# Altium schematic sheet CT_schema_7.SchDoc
size 371 x 336 mm
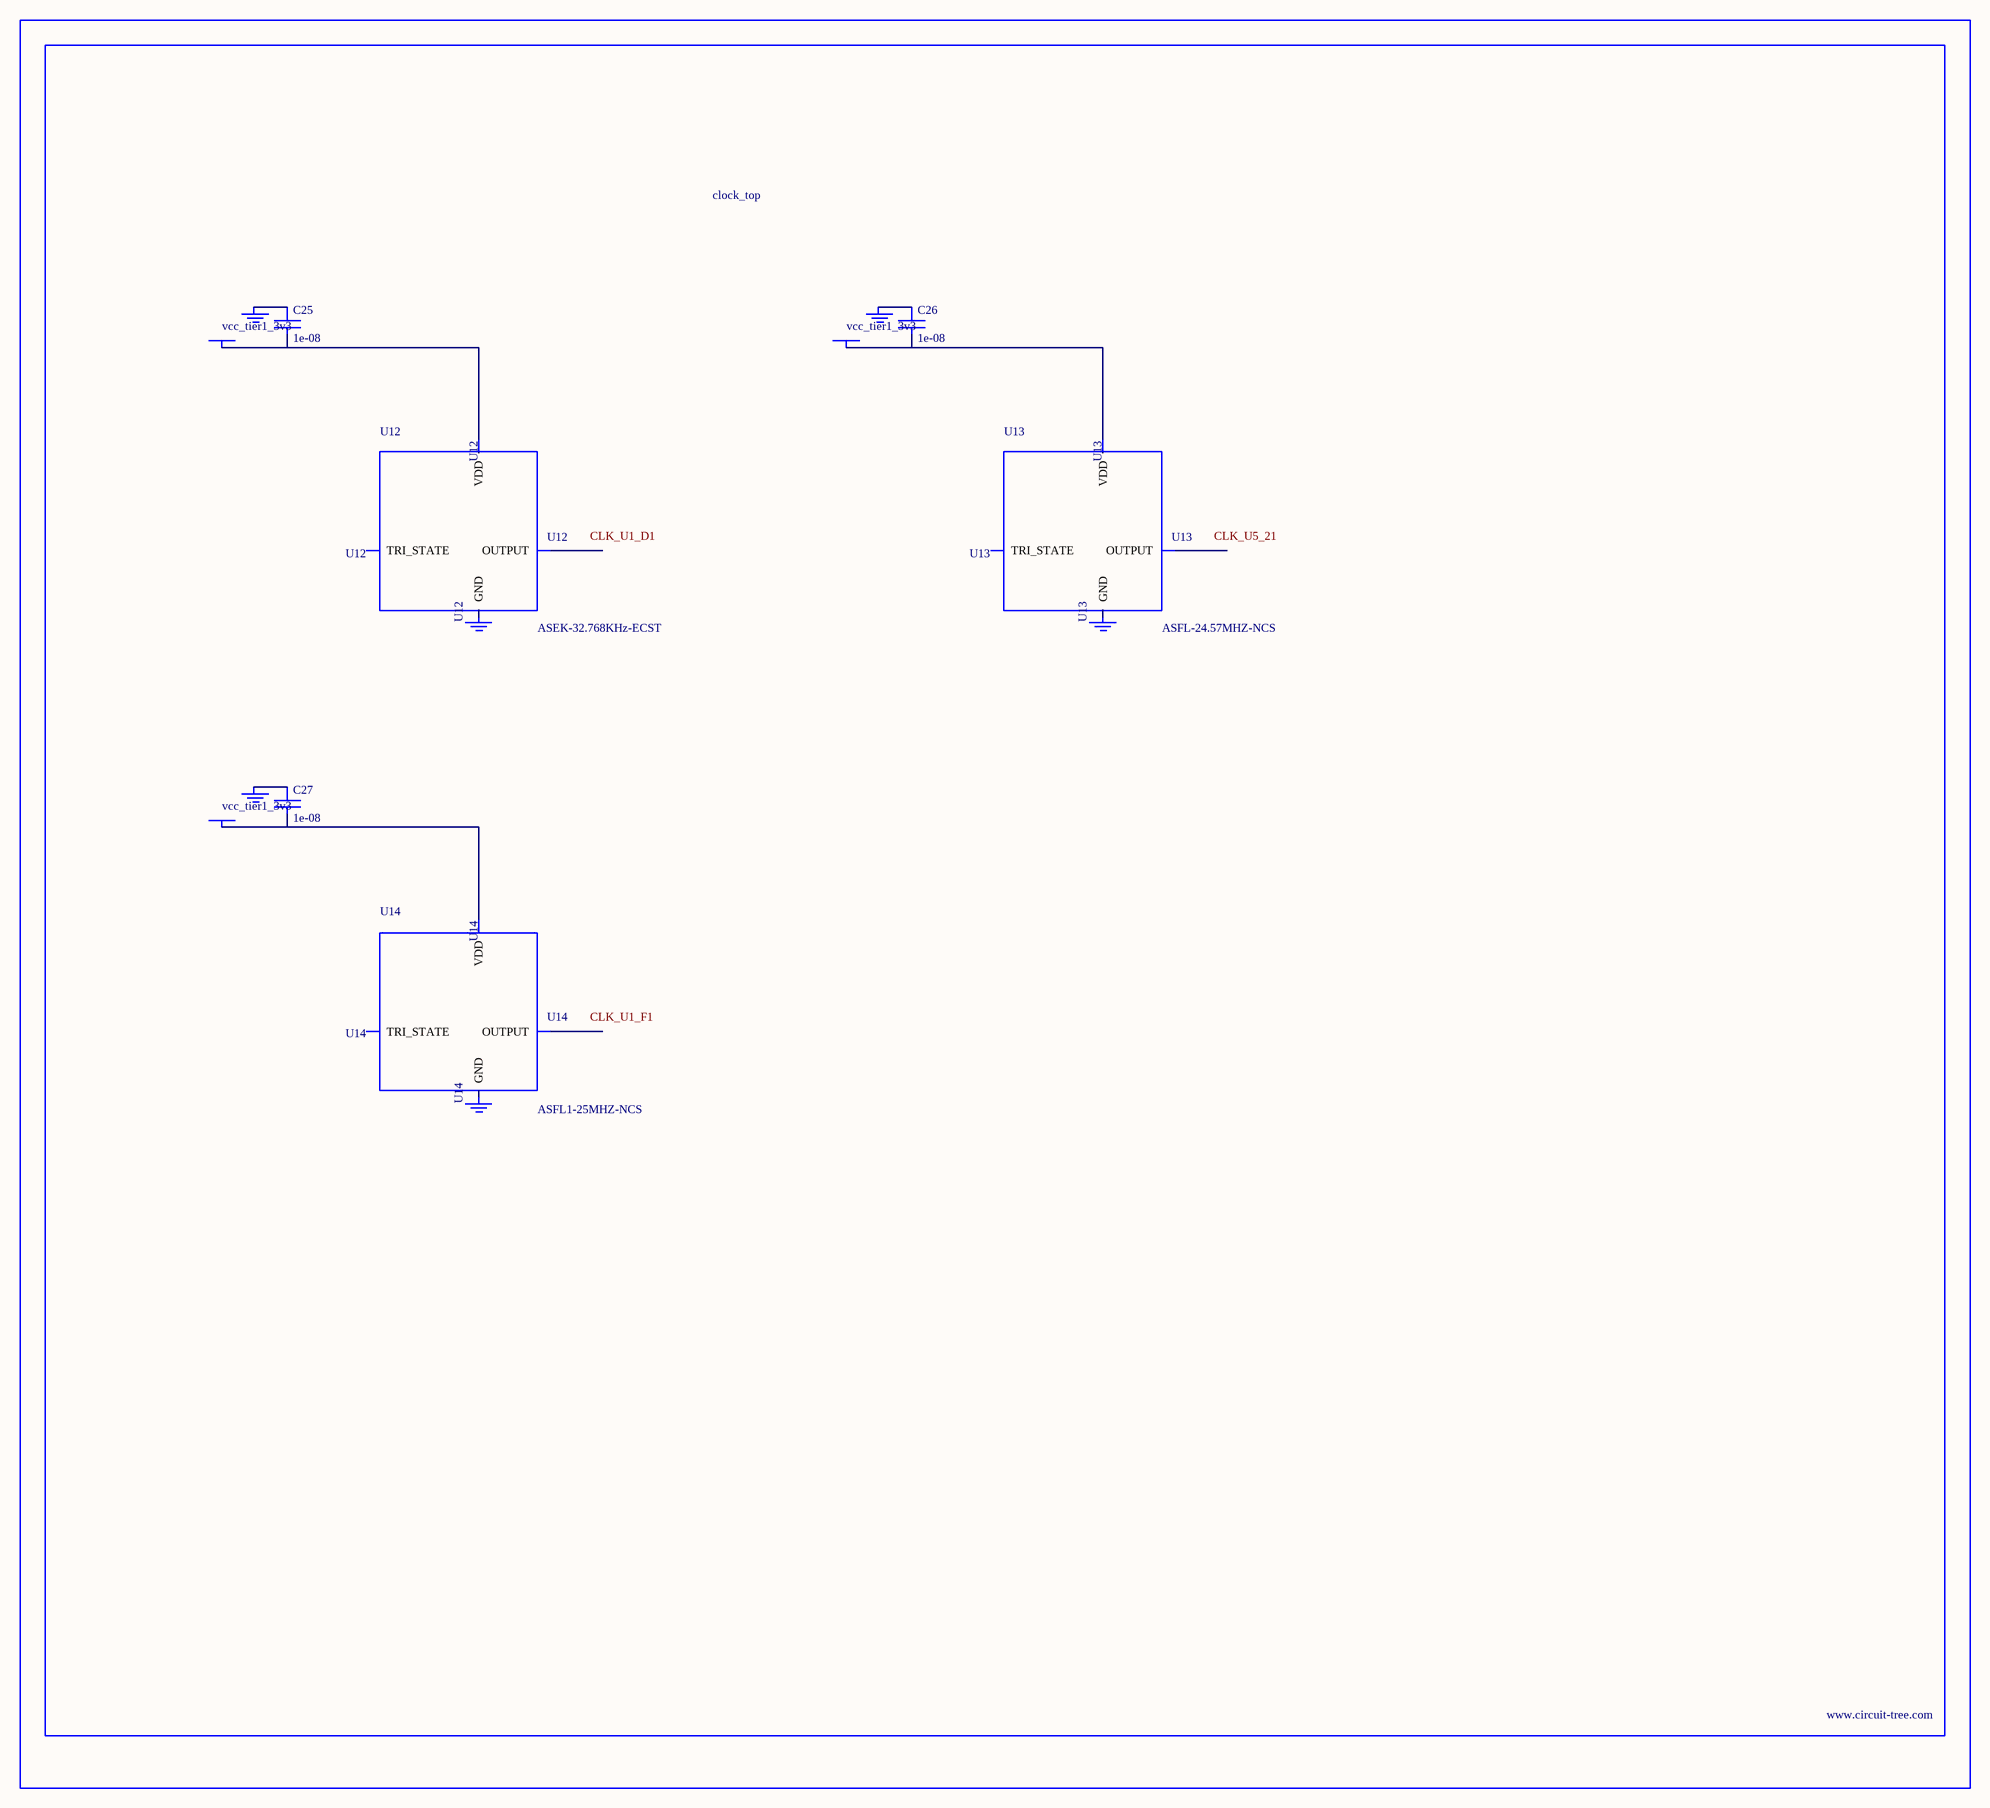
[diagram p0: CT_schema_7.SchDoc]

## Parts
BORDER6  (no value)
C25  1e-08  [C0402]
C26  1e-08  [C0402]
C27  1e-08  [C0402]
GND_INSTANCE_6_0  (no value)
GND_INSTANCE_6_1  (no value)
GND_INSTANCE_6_2  (no value)
GND_INSTANCE_6_3  (no value)
GND_INSTANCE_6_4  (no value)
GND_INSTANCE_6_5  (no value)
POWER_INSTANCE_6_0  vcc_tier1_3v3
POWER_INSTANCE_6_1  vcc_tier1_3v3
POWER_INSTANCE_6_2  vcc_tier1_3v3
U12  ASEK-32.768KHz-ECST  [ASEK]
U13  ASFL-24.57MHZ-NCS  [ASFL1]
U14  ASFL1-25MHZ-NCS  [ASFL1]

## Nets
NetC25_1: C25.1 GND_INSTANCE_6_0.0(GND)
NetC25_2: C25.2 POWER_INSTANCE_6_0.0(PWR) U12.4(VDD)
NetC26_1: C26.1 GND_INSTANCE_6_2.0(GND)
NetC26_2: C26.2 POWER_INSTANCE_6_1.0(PWR) U13.4(VDD)
NetC27_1: C27.1 GND_INSTANCE_6_4.0(GND)
NetC27_2: C27.2 POWER_INSTANCE_6_2.0(PWR) U14.4(VDD)

Not connected (* = marked no-connect by the designer): GND_INSTANCE_6_1 0(GND); GND_INSTANCE_6_3 0(GND); GND_INSTANCE_6_5 0(GND); U12 1(TRI_STATE) 2(GND) 3(OUTPUT); U13 1(TRI_STATE) 2(GND) 3(OUTPUT); U14 1(TRI_STATE) 2(GND) 3(OUTPUT)

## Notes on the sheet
- Labels drawn without touching a wire or pin: CLK_U1_D1, CLK_U1_F1, CLK_U5_21

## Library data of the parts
BORDER6 = BORDER_PAGE6
C25-C27 = C0402C103K3RAC
GND_INSTANCE_6_0-GND_INSTANCE_6_5 = GND
POWER_INSTANCE_6_0-POWER_INSTANCE_6_2 = PWR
